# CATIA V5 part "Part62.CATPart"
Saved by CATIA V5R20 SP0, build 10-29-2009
Part number: FA 042200-2
Revision: ANY
Definition: UNKNOWN
Nomenclature: FA 042200-2
Source: Unknown
Bounding box of the stored display mesh (mm): x -1.5 to 1.5, y 0 to 2.7, z -1.5 to 1.5
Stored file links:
  C:\Users\Utente\Desktop\IO LAVORO\3D X SITO CF\CUMSA\3D files FA\FA 042212-21\Part62.CATPart

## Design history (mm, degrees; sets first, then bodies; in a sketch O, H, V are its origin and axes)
Body1 "Cortar-Extruir1" (main body)
  Solid1: solid without history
